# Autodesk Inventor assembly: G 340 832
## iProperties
Created: 2006-10
Part Number: G 340 832
Document SubType Name: Schweißkonstruktion
Designer: I.Baliuc
Manufacturer: Standard
Standards Organization: Custom
Description: Vorkontakt, kpl.
Material: gelötet
Mass: 154.738 g
Surface Area: 84.4615 cm^2
Volume: 17.2647 cm^3
Density: 8.96272 g/cm^3
Title: Vorkontakt, kompl.
Company: Mayer & Müller AG Schaltgeräte
Author: T.Messerschmitt
Revision Number: 340832
